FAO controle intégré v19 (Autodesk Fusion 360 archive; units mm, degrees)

design "FAO controle intégré" references "BRUT CONTROLE INTEGRE", "tenon", "alesage"
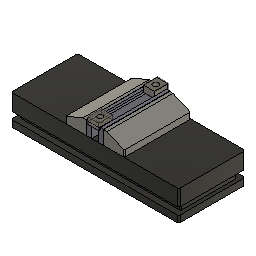
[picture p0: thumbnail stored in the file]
parameter "Ouverture" = 25
base_feature "Base Feature1" OffsetX 0 OffsetY 0 OffsetZ 0 OffsetX 0 OffsetY 0 OffsetZ 0 OffsetX 0 OffsetY 0 OffsetZ 0
base_feature "Base Feature1"
base_feature "Base Feature1" OffsetX 0 OffsetY 0 OffsetZ 0
base_feature "Base Feature1"
base_feature "Base Feature1" OffsetX 0 OffsetY 0 OffsetZ 0 OffsetX 0 OffsetY 0 OffsetZ 0
as_built_joint "As-built1"
as_built_joint "As-built1"
joint "Assemble1" alignOffsetX 0 alignOffsetY 0 alignOffsetZ 7.5 (= "Ouverture / 2 - 5 mm")
joint "Assemble2" alignOffsetX 0 alignOffsetY 0 alignOffsetZ -7.5 (= "-Ouverture / 2 + 5 mm")
component_insert "Insertion d'un composant2"
component_insert "Insertion d'un composant3"
position "Position1"
component_insert "Insertion d'un composant4"
component_insert "Insertion d'un composant5"
position "Position2"
sketch "Esquisse" plane through (0, 0, 100) normal (0, 0, 1) x axis (-1, 0, 0)
  line L1 (-12.5, 75.5) -> (12.5, -74.5)
  point P2 (12.5, -74.5)
  point P4 (12.5, -74.5)
  point P3 (-12.5, 75.5)
  point P5 (-12.5, 75.5)
  point P1 (0, 0)
  point P6 (0, 0)
  coincident P2 P4
  coincident P3 P5
  coincident P1 P6
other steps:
create_component "CreateComponent1"
create_component "CreateComponent2"
create_component "CreateComponent1"
create_component "CreateComponent2"
create_component "CreateComponent3"
create_component "CreateComponent1"
create_component "CreateComponent2"
joint_origin "JointOrigin2" OffsetX 0 OffsetY 0 OffsetZ 0
joint_origin "JointOrigin4" OffsetX 0 OffsetY 0 OffsetZ 0
joint_origin "JointOrigin3" OffsetX 0 OffsetY 0 OffsetZ 0
joint_origin "JointOrigin5" OffsetX 0 OffsetY 0 OffsetZ 0
create_component "CreateComponent1"

design "alesage"
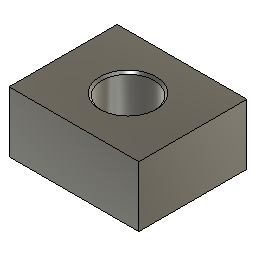
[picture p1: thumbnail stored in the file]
sketch "Esquisse1" plane through (0, 0, 0) normal (0, 0, 1) x axis (1, 0, 0)
  line L1 (30, 0) -> (0, 0)
  line L2 (30, 25) -> (30, 0)
  line L3 (0, 25) -> (30, 25)
  line L4 (0, 0) -> (0, 25)
  point P1 (0, 0)
  point P2 (0, 0)
  point P3 (30, 0)
  point P5 (0, 25)
  horizontal L1
  vertical L2
  horizontal L3
  vertical L4
  coincident P1 P2
  dimension "d1" distance P2 P3 = 30
  dimension "d2" distance P2 P5 = 25
extrude "Extrusion1" new body sketch "Esquisse1" along normal blind 14
sketch "Esquisse2" plane through (0, 0, 14) normal (0, 0, 1) x axis (-1, 0, 0)
  line L1 (-30, 0) -> (0, 0)
  line L2 (0, -25) -> (-30, -25)
  line L3 (-15, -25) -> (-15, 0)
  line L4 (-30, -25) -> (-30, 0)
  line L5 (0, 0) -> (0, -25)
  line L6 (0, -12.5) -> (-30, -12.5)
  circle C1 centre (-15, -12.5) radius 6
  point P7 (-15, 0)
  point P8 (-15, -25)
  point P9 (-30, -12.5)
  point P10 (0, -12.5)
  point P2 (-15, -12.5)
  midpoint L1 P7
  midpoint L2 P8
  midpoint L4 P9
  midpoint L5 P10
  midpoint P2 L6
  dimension "d5" diameter C1 = 12
extrude "Extrusion3" cut sketch "Esquisse2" profile of C1 against normal blind 9
chamfer "Chanfrein" distance 0.5
offset_faces "DécalerLesFaces" distance -0.009

design "BRUT CONTROLE INTEGRE"
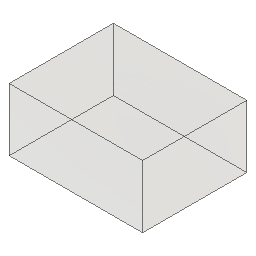
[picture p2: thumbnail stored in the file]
sketch "Esquisse" plane through (0, 0, 0) normal (0, 0, 1) x axis (1, 0, 0)
  line L1 (32, 0) -> (0, 0)
  line L2 (32, 25) -> (32, 0)
  line L3 (0, 25) -> (32, 25)
  line L4 (0, 0) -> (0, 25)
  point P1 (0, 0)
  point P2 (0, 0)
  point P3 (32, 0)
  point P5 (0, 25)
  horizontal L1
  vertical L2
  horizontal L3
  vertical L4
  coincident P1 P2
  dimension "d1" distance P2 P3 = 32
  dimension "d2" distance P2 P5 = 25
extrude "Extrusion" new body sketch "Esquisse" along normal blind 15

design "tenon"
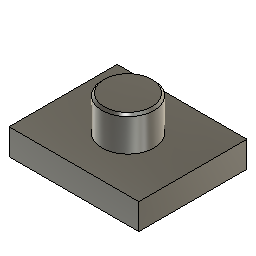
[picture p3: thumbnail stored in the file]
sketch "Esquisse1" plane through (0, 0, 0) normal (0, 0, 1) x axis (1, 0, 0)
  line L1 (30, 0) -> (0, 0)
  line L2 (30, 25) -> (30, 0)
  line L3 (0, 25) -> (30, 25)
  line L4 (0, 0) -> (0, 25)
  point P1 (0, 0)
  point P2 (0, 0)
  point P3 (30, 0)
  point P5 (0, 25)
  horizontal L1
  vertical L2
  horizontal L3
  vertical L4
  coincident P1 P2
  dimension "d1" distance P2 P3 = 30
  dimension "d2" distance P2 P5 = 25
extrude "Extrusion1" new body sketch "Esquisse1" along normal blind 6
sketch "Esquisse2" plane through (0, 0, 6) normal (0, 0, 1) x axis (-1, 0, 0)
  line L1 (-30, 0) -> (0, 0)
  line L2 (0, -25) -> (-30, -25)
  line L3 (-15, -25) -> (-15, 0)
  line L4 (-30, -25) -> (-30, 0)
  line L5 (0, 0) -> (0, -25)
  line L6 (0, -12.5) -> (-30, -12.5)
  circle C1 centre (-15, -12.5) radius 6
  point P7 (-15, 0)
  point P8 (-15, -25)
  point P9 (-30, -12.5)
  point P10 (0, -12.5)
  point P2 (-15, -12.5)
  midpoint L1 P7
  midpoint L2 P8
  midpoint L4 P9
  midpoint L5 P10
  midpoint P2 L6
  dimension "d5" diameter C1 = 12
extrude "Extrusion2" add sketch "Esquisse2" profile of C1 along normal blind 8
chamfer "Chanfrein" distance 0.5
offset_faces "DécalerLesFaces" distance -0.01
